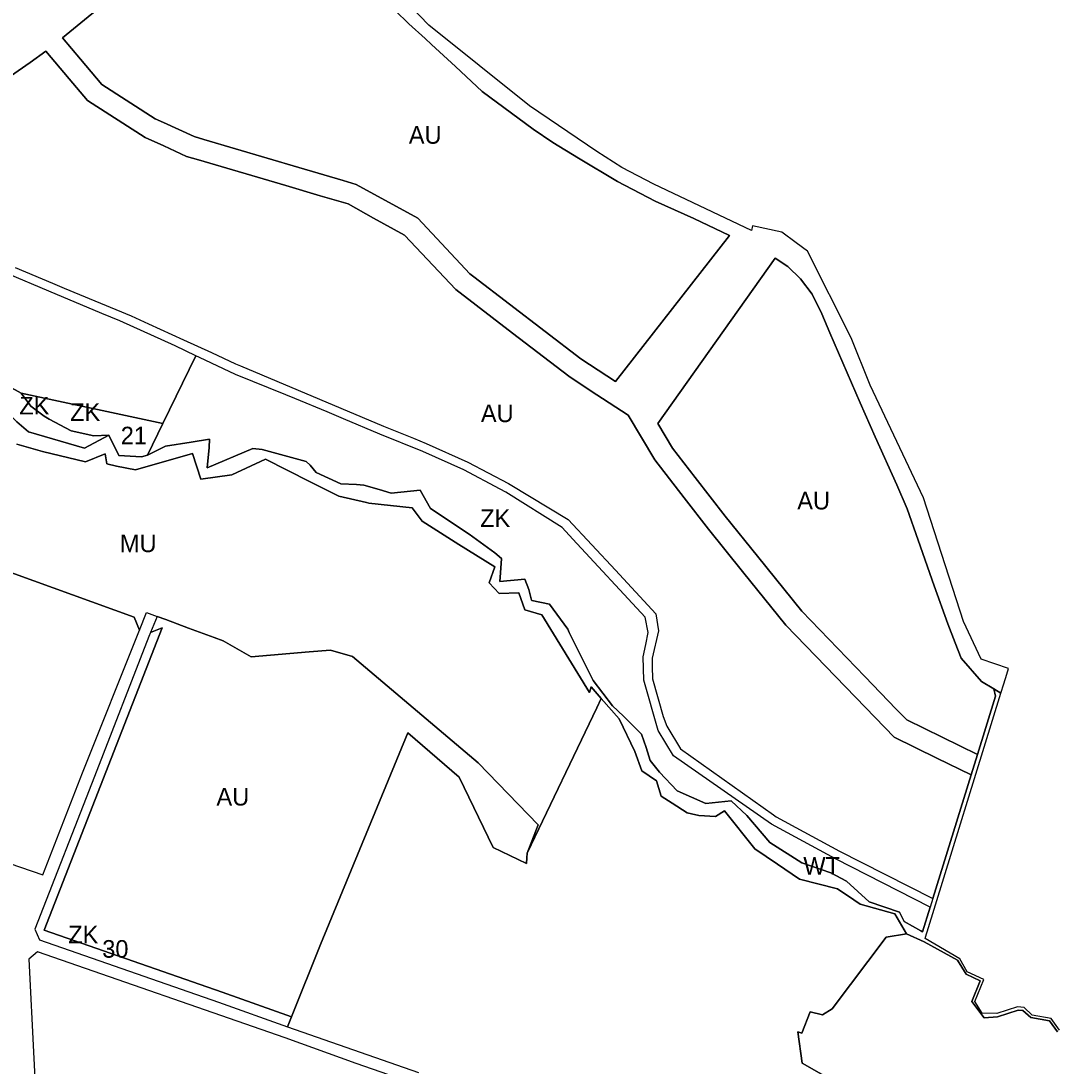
# Model space of a CAD drawing. Extents: x -522079 to -518833, y -1142398 to -1139961.
# Drawn here: x -520015 to -519428, y -1141332 to -1140739 of the extents above; entities that cross this region are included whole.
import ezdxf

# ---------------------------------------------------------------- set-up
doc = ezdxf.new("R2010")
doc.units = 0
for name, color, linetype in [('90640013', 7, 'Continuous'), ('90710013', 7, 'Continuous'), ('90710023', 7, 'Continuous'), ('90730013', 7, 'Continuous'), ('90750013', 7, 'Continuous'), ('90770013', 7, 'Continuous'), ('90830013', 7, 'Continuous'), ('ID_navrh', 7, 'Continuous')]:
    doc.layers.add(name, color=color, linetype=linetype)

msp = doc.modelspace()

# ---------------------------------------------------------------- linework, layer by layer
at = {"layer": '90640013'}
for points in [[(-519426.16, -1141311.48), (-519430.99, -1141304.77), (-519441.7, -1141302.87), (-519446.22, -1141298.48), (-519449.98, -1141298.09), (-519461.74, -1141302), (-519470.14, -1141301.74), (-519474.2, -1141295.1), (-519469.18, -1141282.65), (-519478.58, -1141278.28), (-519482.78, -1141270.88), (-519502.46, -1141259.44), (-519501.64, -1141256.67), (-519501.33, -1141255.67), (-519459.37, -1141120.07), (-519463.51, -1141117.64), (-519462.56, -1141121.92), (-519472.79, -1141154.97), (-519476.38, -1141166.58), (-519498.1, -1141236.79), (-519499.59, -1141241.58), (-519503.9, -1141255.56), (-519504.82, -1141255.11), (-519514.28, -1141249.74), (-519516.96, -1141244.4), (-519534.2, -1141238.58), (-519546.94, -1141226.78), (-519555.86, -1141222.18), (-519572.33, -1141216.46), (-519590.58, -1141204.82), (-519603.54, -1141189.56), (-519612.48, -1141181.23), (-519626.9, -1141182.72), (-519643.13, -1141175.65), (-519653.03, -1141164.92), (-519658.41, -1141158.35), (-519660.65, -1141151.03), (-519663.4, -1141143.35), (-519673.55, -1141133.3), (-519679.71, -1141127.39), (-519690.7, -1141113), (-519704.33, -1141085.64), (-519704.67, -1141084.75), (-519705.02, -1141083.87), (-519715.52, -1141069.7), (-519725.48, -1141067.48), (-519725.71, -1141067.43), (-519727.24, -1141061.4), (-519729.57, -1141055.46), (-519743.63, -1141056.81), (-519743.3, -1141051.84), (-519742.77, -1141043.74), (-519746.47, -1141040.52), (-519761.05, -1141030.01), (-519783.07, -1141015.31), (-519788.8, -1141004.86), (-519805.33, -1141006.69), (-519812.07, -1141004.64), (-519820.93, -1141002.11), (-519825.01, -1141001.81), (-519833.92, -1141001.35), (-519847.96, -1140994.97), (-519851.21, -1140990.81), (-519853.55, -1140988.6), (-519878.53, -1140981.83), (-519883.85, -1140981.36), (-519909.8, -1140992.3), (-519908.53, -1140980.82), (-519908.41, -1140976.07), (-519918.88, -1140977.69), (-519933.4, -1140979.93), (-519943.51, -1140985.08), (-519947.03, -1140986.05), (-519959.93, -1140985.31), (-519965.47, -1140973.69), (-519979.37, -1140981.19), (-520011.16, -1140971.75), (-520017.69, -1140966.19)], [(-520017.73, -1140978.78), (-520003.11, -1140982.94), (-519978.85, -1140988.86), (-519967.54, -1140984.38), (-519966.67, -1140989.91), (-519961.08, -1140991.39), (-519950.36, -1140993.42), (-519918.04, -1140984.12), (-519913.39, -1140998.68), (-519895.77, -1140996.31), (-519876.6, -1140987.29), (-519851.59, -1141000.07), (-519835.08, -1141008.27), (-519819.26, -1141011.99), (-519818.09, -1141012.26), (-519793.36, -1141014.98), (-519787.79, -1141022.58), (-519766.87, -1141035.85), (-519746.51, -1141048.43), (-519749.67, -1141057.47), (-519744.08, -1141063.56), (-519732.93, -1141063.24), (-519729.51, -1141072.8), (-519719.95, -1141075.61), (-519692.8, -1141119.72), (-519691.83, -1141116.63), (-519686.19, -1141123.12), (-519676.06, -1141134.77), (-519667.13, -1141153.28), (-519663.19, -1141164.28), (-519654.81, -1141169.94), (-519652.19, -1141178.57), (-519646.01, -1141182.51), (-519637.37, -1141188.02), (-519635, -1141188.59), (-519630.7, -1141189.62), (-519621.3, -1141190.09), (-519616.23, -1141186.99), (-519599.05, -1141208.49), (-519586.25, -1141217.21), (-519573.7, -1141225.77), (-519552.03, -1141231.12), (-519542.77, -1141237.45), (-519539.27, -1141239.84), (-519519.64, -1141245.38), (-519512.96, -1141256.69), (-519502.94, -1141261.24), (-519484.08, -1141271.62), (-519479.21, -1141279.64), (-519471.1, -1141283.41), (-519475.87, -1141295.24), (-519468.94, -1141304.33), (-519461.31, -1141303.85), (-519449.71, -1141299.98), (-519446.9, -1141300.29), (-519442.41, -1141304.27), (-519431.85, -1141306.14), (-519427.38, -1141312.36)]]:
    msp.add_lwpolyline(points, dxfattribs=at)
at = {"layer": '90710013'}
for points in [[(-519818.61, -1140717.36), (-519795.23, -1140740.19), (-519786.12, -1140748.61), (-519782.42, -1140752.04), (-519768.84, -1140764.57), (-519753.73, -1140778.67), (-519724.7, -1140800.07), (-519713.71, -1140807.66), (-519698.98, -1140816.54), (-519677.02, -1140829.78), (-519655.55, -1140840.89), (-519633.63, -1140850.83), (-519613.39, -1140860.38), (-519678.04, -1140943.34), (-519697.68, -1140930.5), (-519758.42, -1140883.91), (-519760.64, -1140882.2), (-519790.25, -1140850.67), (-519825.13, -1140831.39), (-519832.56, -1140829.21), (-519857.7, -1140821.8), (-519911.71, -1140805.9), (-519917.19, -1140804.28), (-519934.47, -1140796.36), (-519939.19, -1140794.19), (-519969.55, -1140774.7), (-519981.63, -1140760.4), (-519991.87, -1140748.27), (-519893.23, -1140667.47)], [(-520068.52, -1140802.68), (-520010.06, -1140762.16), (-520001.24, -1140755.77), (-519987.93, -1140771.54), (-519977.56, -1140783.82), (-519944.96, -1140804.75), (-519934.39, -1140809.6), (-519921.41, -1140815.55), (-519914.69, -1140817.53), (-519865.19, -1140832.11), (-519845.71, -1140837.84), (-519829.78, -1140842.53), (-519815.37, -1140850.5), (-519797.7, -1140860.26), (-519768.72, -1140891.13), (-519736.43, -1140915.9), (-519704.63, -1140940.29), (-519692.38, -1140948.3), (-519670.91, -1140962.34), (-519655.67, -1140987.81), (-519639.1, -1141009.23), (-519625.22, -1141027.17), (-519605.96, -1141051.06), (-519581.39, -1141081.54), (-519536.28, -1141128.25), (-519519.99, -1141145.11), (-519495.79, -1141157.02), (-519476.38, -1141166.58), (-519472.79, -1141154.97), (-519512.81, -1141135.27), (-519518.89, -1141129.28), (-519536.59, -1141110.65), (-519572.39, -1141073.59), (-519597.55, -1141042.38), (-519615.79, -1141019.75), (-519632.87, -1140997.67), (-519645.74, -1140981.03), (-519654.13, -1140967.02), (-519587.52, -1140873.31), (-519580.34, -1140878), (-519573.15, -1140884.93), (-519566.48, -1140893.71), (-519561.03, -1140904.86), (-519556.41, -1140915.6), (-519539.28, -1140955.41), (-519530.67, -1140974.63), (-519518.48, -1141001.84), (-519512.69, -1141015.45), (-519506.32, -1141033.4), (-519497.19, -1141059.15), (-519489.53, -1141080.75), (-519485.33, -1141091.52), (-519481.95, -1141100.21), (-519470.4, -1141113.6), (-519463.51, -1141117.64), (-519459.37, -1141120.07), (-519457.77, -1141114.91), (-519456.05, -1141109.33), (-519455.06, -1141106.14), (-519470.66, -1141100.87), (-519480.71, -1141079.48), (-519503.31, -1141009.21), (-519533.66, -1140945.39), (-519544.31, -1140918.54), (-519569.14, -1140869.38), (-519575.54, -1140864.6), (-519583.72, -1140858.5), (-519600.42, -1140854.95), (-519600.86, -1140857.49), (-519656.36, -1140831.22), (-519674.4, -1140821.79), (-519688.67, -1140812.79), (-519726.89, -1140786.75), (-519783.91, -1140740.96), (-519820.17, -1140703.4)]]:
    msp.add_lwpolyline(points, dxfattribs=at)
for points in [[(-520015.17, -1140949.95), (-520029.76, -1140941.98), (-520046.33, -1140932.29), (-520051.93, -1140931.48), (-520017.69, -1140966.19), (-520011.16, -1140971.75), (-519979.37, -1140981.19), (-519965.47, -1140973.69), (-519974.08, -1140974.02), (-519986.94, -1140971.3), (-519999.3, -1140964.63), (-520002.28, -1140962.91), (-520009.84, -1140957.29)], [(-519943.51, -1140985.08), (-519933.4, -1140979.93), (-519918.88, -1140977.69), (-519908.41, -1140976.07), (-519908.53, -1140980.82), (-519909.8, -1140992.3), (-519883.85, -1140981.36), (-519878.53, -1140981.83), (-519853.55, -1140988.6), (-519851.21, -1140990.81), (-519847.96, -1140994.97), (-519833.92, -1141001.35), (-519825.01, -1141001.81), (-519820.93, -1141002.11), (-519812.07, -1141004.64), (-519805.33, -1141006.69), (-519788.8, -1141004.86), (-519783.07, -1141015.31), (-519761.05, -1141030.01), (-519746.47, -1141040.52), (-519742.77, -1141043.74), (-519743.3, -1141051.84), (-519743.63, -1141056.81), (-519729.57, -1141055.46), (-519727.24, -1141061.4), (-519725.71, -1141067.43), (-519725.48, -1141067.48), (-519715.52, -1141069.7), (-519705.02, -1141083.87), (-519704.67, -1141084.75), (-519704.33, -1141085.64), (-519690.7, -1141113), (-519679.71, -1141127.39), (-519673.55, -1141133.3), (-519663.4, -1141143.35), (-519660.65, -1141151.03), (-519658.41, -1141158.35), (-519653.03, -1141164.92), (-519643.13, -1141175.65), (-519626.9, -1141182.72), (-519612.48, -1141181.23), (-519603.54, -1141189.56), (-519590.58, -1141204.82), (-519572.33, -1141216.46), (-519555.86, -1141222.18), (-519546.94, -1141226.78), (-519534.2, -1141238.58), (-519516.96, -1141244.4), (-519514.28, -1141249.74), (-519504.82, -1141255.11), (-519503.9, -1141255.56), (-519499.59, -1141241.58), (-519553.27, -1141214.2), (-519589.6, -1141194.6), (-519645.14, -1141155.67), (-519653.82, -1141141.35), (-519662.06, -1141112.71), (-519662.35, -1141099.54), (-519660.92, -1141092.62), (-519659.49, -1141085.69), (-519661.22, -1141076.98), (-519702.3, -1141032.7), (-519708.41, -1141026.12), (-519740.29, -1141006.03), (-519743.47, -1141004.35), (-519764.04, -1140993.49), (-519787.36, -1140982.97), (-519811.83, -1140973.18), (-519832.3, -1140964.53), (-519841.67, -1140960.58), (-519859.94, -1140952.86), (-519865.12, -1140950.76), (-519893.61, -1140939.25), (-519914.16, -1140929.63), (-519916.21, -1140928.63), (-519934.8, -1140967.08)]]:
    msp.add_lwpolyline(points, close=True, dxfattribs=at)
at = {"layer": '90710023'}
msp.add_lwpolyline([(-520015.17, -1140949.95), (-520009.84, -1140957.29), (-520002.28, -1140962.91), (-519999.3, -1140964.63), (-519986.94, -1140971.3), (-519974.08, -1140974.02), (-519965.47, -1140973.69), (-519959.93, -1140985.31), (-519947.03, -1140986.05), (-519943.51, -1140985.08), (-519934.8, -1140967.08)], close=True, dxfattribs=at)
msp.add_lwpolyline([(-519941.9, -1141085.78), (-519942.77, -1141088.03), (-519973.57, -1141167.53), (-520007.53, -1141254.06), (-520004.78, -1141260.17), (-519903.26, -1141295.46), (-519864.09, -1141309.46), (-519861.86, -1141303.89), (-519901.27, -1141289.8), (-520002.16, -1141254.73), (-519935.26, -1141083.16), (-519941.89, -1141085.78), (-519941.9, -1141085.78)], dxfattribs=at)
at = {"layer": '90730013'}
for points in [[(-519512.96, -1141256.69), (-519524.47, -1141258.63), (-519555.19, -1141299.24), (-519560.68, -1141302.79), (-519567.64, -1141300.94), (-519572.4, -1141313.2), (-519574.58, -1141312.28), (-519572.25, -1141330.06), (-519526.67, -1141356.01), (-519507.9, -1141366.28), (-519493.9, -1141370.24), (-519494.92, -1141380.6), (-519488.36, -1141388.76), (-519489.99, -1141393.96), (-519496.45, -1141402.69), (-519490.7, -1141404.57), (-519466.91, -1141416.21), (-519450.75, -1141420.94), (-519402.53, -1141416.1)], [(-519427.38, -1141312.36), (-519431.85, -1141306.14), (-519442.41, -1141304.27), (-519446.9, -1141300.29), (-519449.71, -1141299.98), (-519461.31, -1141303.85), (-519468.94, -1141304.33), (-519475.87, -1141295.24), (-519471.1, -1141283.41), (-519479.21, -1141279.64), (-519484.08, -1141271.62), (-519502.94, -1141261.24), (-519512.96, -1141256.69)]]:
    msp.add_lwpolyline(points, dxfattribs=at)
at = {"layer": '90750013'}
for points in [[(-519893.23, -1140667.47), (-519991.87, -1140748.27), (-519981.63, -1140760.4), (-519969.55, -1140774.7), (-519939.19, -1140794.19), (-519934.47, -1140796.36), (-519917.19, -1140804.28), (-519911.71, -1140805.9), (-519857.7, -1140821.8), (-519832.56, -1140829.21), (-519825.13, -1140831.39), (-519790.25, -1140850.67), (-519760.64, -1140882.2), (-519758.42, -1140883.91), (-519697.68, -1140930.5), (-519678.04, -1140943.34), (-519613.39, -1140860.38), (-519633.63, -1140850.83), (-519655.55, -1140840.89), (-519677.02, -1140829.78), (-519698.98, -1140816.54), (-519713.71, -1140807.66), (-519724.7, -1140800.07), (-519753.73, -1140778.67), (-519768.84, -1140764.57), (-519782.42, -1140752.04), (-519786.12, -1140748.61), (-519795.23, -1140740.19), (-519818.61, -1140717.36)], [(-520018.57, -1140878.52), (-519997.49, -1140887.4), (-519990.79, -1140890.22), (-519952.82, -1140906.1), (-519943.08, -1140910.55), (-519923.13, -1140919.66), (-519907.29, -1140926.89), (-519893.61, -1140933.19), (-519890.83, -1140934.46), (-519858.03, -1140948.23), (-519809.71, -1140968.63), (-519792.75, -1140975.43), (-519785.4, -1140978.37), (-519761.84, -1140988.99), (-519738.84, -1141001.14), (-519737.76, -1141001.71), (-519704.97, -1141021.67), (-519678.16, -1141050.41), (-519655.12, -1141075.09), (-519653.67, -1141084.78), (-519657.33, -1141100.32), (-519657.23, -1141105.11), (-519657.08, -1141111.95), (-519650.97, -1141133.45), (-519648.88, -1141138.93), (-519641.2, -1141151.84), (-519588.4, -1141189.29), (-519586.93, -1141190.33), (-519550.99, -1141209.75), (-519538.78, -1141215.99), (-519498.1, -1141236.79), (-519476.38, -1141166.58), (-519495.79, -1141157.02), (-519519.99, -1141145.11), (-519536.28, -1141128.25), (-519581.39, -1141081.54), (-519605.96, -1141051.06), (-519625.22, -1141027.17), (-519639.1, -1141009.23), (-519655.67, -1140987.81), (-519670.91, -1140962.34), (-519692.38, -1140948.3), (-519704.63, -1140940.29), (-519736.43, -1140915.9), (-519768.72, -1140891.13), (-519797.7, -1140860.26), (-519815.37, -1140850.5), (-519829.78, -1140842.53), (-519845.71, -1140837.84), (-519865.19, -1140832.11), (-519914.69, -1140817.53), (-519921.41, -1140815.55), (-519934.39, -1140809.6), (-519944.96, -1140804.75), (-519977.56, -1140783.82), (-519987.93, -1140771.54), (-520001.24, -1140755.77), (-520010.06, -1140762.16), (-520068.52, -1140802.68)], [(-519463.51, -1141117.64), (-519470.4, -1141113.6), (-519481.95, -1141100.21), (-519485.33, -1141091.52), (-519489.53, -1141080.75), (-519497.19, -1141059.15), (-519506.32, -1141033.4), (-519512.69, -1141015.45), (-519518.48, -1141001.84), (-519530.67, -1140974.63), (-519539.28, -1140955.41), (-519556.41, -1140915.6), (-519561.03, -1140904.86), (-519566.48, -1140893.71), (-519573.15, -1140884.93), (-519580.34, -1140878), (-519587.52, -1140873.31), (-519654.13, -1140967.02), (-519645.74, -1140981.03), (-519632.87, -1140997.67), (-519615.79, -1141019.75), (-519597.55, -1141042.38), (-519572.39, -1141073.59), (-519536.59, -1141110.65), (-519518.89, -1141129.28), (-519512.81, -1141135.27), (-519472.79, -1141154.97), (-519462.56, -1141121.92), (-519463.51, -1141117.64)], [(-519941.9, -1141085.78), (-519941.89, -1141085.78), (-519935.26, -1141083.16), (-520002.16, -1141254.73), (-519901.27, -1141289.8), (-519861.86, -1141303.89), (-519845.38, -1141262.74), (-519795.94, -1141142.67), (-519766.69, -1141167.92), (-519747.5, -1141207.73), (-519728.58, -1141216.84), (-519728.39, -1141213.65), (-519728.23, -1141211.06), (-519723.28, -1141198.33), (-519721.93, -1141194.85), (-519756.03, -1141159.77), (-519800.19, -1141122.28), (-519827.19, -1141099.4), (-519839.81, -1141095.68), (-519851.93, -1141096.73), (-519884.82, -1141099.57), (-519900.64, -1141090.45), (-519905.71, -1141088.58), (-519920.33, -1141083.18), (-519933.25, -1141078.41), (-519938.17, -1141076.59), (-519941.9, -1141085.78)], [(-519793.08, -1141341.43), (-519825.24, -1141330.38), (-519865.42, -1141315.8), (-520005.98, -1141266.96), (-520010.89, -1141271.2), (-520005.29, -1141383.92)]]:
    msp.add_lwpolyline(points, dxfattribs=at)
msp.add_lwpolyline([(-520194.38, -1141159.65), (-520143.75, -1141175.06), (-520002.99, -1141223.35), (-519980.55, -1141165.39), (-519948.1, -1141084.44), (-519951.21, -1141077.01), (-520032.33, -1141047.7), (-520079.53, -1141019.58), (-520170.88, -1140963.13), (-520205.51, -1141057.7), (-520200.4, -1141059.73), (-520235.62, -1141148.58)], close=True, dxfattribs=at)
at = {"layer": '90770013'}
msp.add_lwpolyline([(-519526.67, -1141356.01), (-519572.25, -1141330.06), (-519574.58, -1141312.28), (-519572.4, -1141313.2), (-519567.64, -1141300.94), (-519560.68, -1141302.79), (-519555.19, -1141299.24), (-519524.47, -1141258.63), (-519512.96, -1141256.69), (-519519.64, -1141245.38), (-519539.27, -1141239.84), (-519542.77, -1141237.45), (-519552.03, -1141231.12), (-519573.7, -1141225.77), (-519586.25, -1141217.21), (-519599.05, -1141208.49), (-519616.23, -1141186.99), (-519621.3, -1141190.09), (-519630.7, -1141189.62), (-519635, -1141188.59), (-519637.37, -1141188.02), (-519646.01, -1141182.51), (-519652.19, -1141178.57), (-519654.81, -1141169.94), (-519663.19, -1141164.28), (-519667.13, -1141153.28), (-519676.06, -1141134.77), (-519686.19, -1141123.12), (-519688.75, -1141128.51), (-519728.23, -1141211.06), (-519728.39, -1141213.65), (-519728.58, -1141216.84), (-519747.5, -1141207.73), (-519766.69, -1141167.92), (-519795.94, -1141142.67), (-519845.38, -1141262.74), (-519861.86, -1141303.89), (-519864.09, -1141309.46), (-519789.84, -1141335.36)], dxfattribs=at)
at = {"layer": '90830013'}
for points in [[(-520029.76, -1140941.98), (-520015.17, -1140949.95), (-519934.8, -1140967.08), (-519916.21, -1140928.63), (-519927.83, -1140922.94), (-519959.29, -1140908.89), (-519969.45, -1140904.62), (-519999.48, -1140892), (-520022.73, -1140882.19)], [(-520032.33, -1141047.7), (-519951.21, -1141077.01), (-519948.1, -1141084.44), (-519944.08, -1141074.41), (-519938.17, -1141076.59), (-519933.25, -1141078.41), (-519920.33, -1141083.18), (-519905.71, -1141088.58), (-519900.64, -1141090.45), (-519884.82, -1141099.57), (-519851.93, -1141096.73), (-519839.81, -1141095.68), (-519827.19, -1141099.4), (-519800.19, -1141122.28), (-519756.03, -1141159.77), (-519721.93, -1141194.85), (-519723.28, -1141198.33), (-519728.23, -1141211.06), (-519688.75, -1141128.51), (-519686.19, -1141123.12), (-519691.83, -1141116.63), (-519692.8, -1141119.72), (-519719.95, -1141075.61), (-519729.51, -1141072.8), (-519732.93, -1141063.24), (-519744.08, -1141063.56), (-519749.67, -1141057.47), (-519746.51, -1141048.43), (-519766.87, -1141035.85), (-519787.79, -1141022.58), (-519793.36, -1141014.98), (-519818.09, -1141012.26), (-519819.26, -1141011.99), (-519835.08, -1141008.27), (-519851.59, -1141000.07), (-519876.6, -1140987.29), (-519895.77, -1140996.31), (-519913.39, -1140998.68), (-519918.04, -1140984.12), (-519950.36, -1140993.42), (-519961.08, -1140991.39), (-519966.67, -1140989.91), (-519967.54, -1140984.38), (-519978.85, -1140988.86), (-520003.11, -1140982.94), (-520017.73, -1140978.78)]]:
    msp.add_lwpolyline(points, dxfattribs=at)

# ---------------------------------------------------------------- texts
at = {"layer": '90640013'}
msp.add_text('WT', height=10, rotation=0, dxfattribs=at).set_placement((-519571.51, -1141223.23))
at = {"layer": '90710013'}
for p in [(-520016.34, -1140961.98), (-519754.86, -1141025.87)]:
    msp.add_text('ZK', height=10, rotation=0, dxfattribs=at).set_placement(p)
at = {"layer": '90710023'}
for rotation, p in [(0, (-519987.47, -1140965.66)), (360, (-519988.57, -1141262.18))]:
    msp.add_text('ZK', height=10, rotation=rotation, dxfattribs=at).set_placement(p)
at = {"layer": '90750013'}
for rotation, p in [(0, (-519795.35, -1140808.34)), (0, (-519754.43, -1140966.34)), (0, (-519574.96, -1141015.89)), (360, (-519904.47, -1141183.94))]:
    msp.add_text('AU', height=10, rotation=rotation, dxfattribs=at).set_placement(p)
at = {"layer": '90830013'}
msp.add_text('MU', height=10, rotation=360, dxfattribs=at).set_placement((-519959.25, -1141040.14))
at = {"layer": 'ID_navrh'}
for s, p in [('21', (-519958.76, -1140978.95)), ('30', (-519969.25, -1141270.3))]:
    msp.add_text(s, height=10, rotation=0, dxfattribs=at).set_placement(p)

doc.saveas('drawing.dxf')
